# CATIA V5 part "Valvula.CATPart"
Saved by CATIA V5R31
Part number: Valvula
Bounding box of the stored display mesh (mm): x -24 to 24, y -34.5 to 30, z -3.804 to 3.804
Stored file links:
  C:\Users\189361\Desktop\comedero, planos\Valvula.CATPart
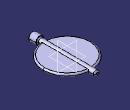
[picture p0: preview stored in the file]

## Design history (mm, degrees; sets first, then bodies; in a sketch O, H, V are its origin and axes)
Set1 "sketch"
  Sketch1 on xy-plane, origin (0, 0, 0), H (1, 0, 0), V (0, 1, 0)
    circle A1 centre (0, 0) radius 24
    radius A1 = 24
  Sketch2 on zx-plane, origin (0, 0, 0), H (-1, 0, 0), V (0, 0, 1)
    circle A1 centre (0, 0) radius 2.5
    radius A1 = 2.5
  Sketch3 on start face of Pad2, origin (0, -27.5, 0), H (1, 0, 0), V (0, 0, 1)
    circle A1 centre (0, 0) radius 4
    construction circle A2 centre (0.1486, 0.4344) radius 3.1
    radius A1 = 4
    radius A2 = 3.1
  Sketch4 on end face of Pad3, origin (0, -34.5, 0), H (1, 0, 0), V (0, 0, 1)
    circle A1 centre (0, 0) radius 3.1
    reference projected circle E1 centre (0, 0) radius 4 from edge [face of Pad3 from Sketch3.A1 | end face of Pad3]
    radius A1 = 3.1
    concentricity: E1 A1
Body1 (main body)
  Pad1: profile Sketch1, direction (0, 0, 1), length 1.5, opposite side length 1.5
  Pad2: profile Sketch2, direction (0, 1, 0), length 30, opposite side length 27.5
  Pad3: profile Sketch3, direction (0, -1, 0), length 7
  Pocket1: profile Sketch4, direction (0, 1, 0), length 5
  Fillet1: radius 1, on edge [start face of Pad3 | face of Pad2 from Sketch2.A1]
  Fillet2: radius 1.5, on edge [face of Pad1 from Sketch1.A1 | end face of Pad1]; edge [start face of Pad1 | face of Pad1 from Sketch1.A1]
  Fillet3: radius 1.5, on edge [face of Pad2 from Sketch2.A1 | end face of Pad2]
